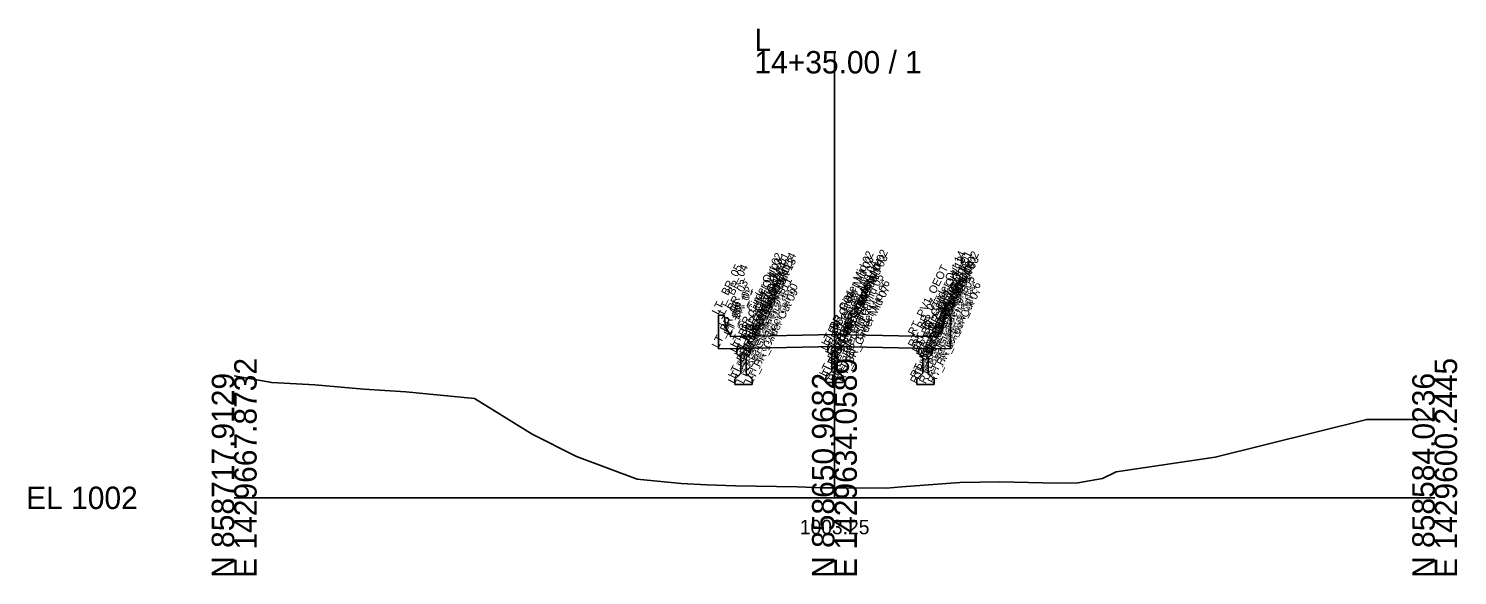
# Model space of a CAD drawing. Extents: x -26 to 2303, y -10 to 19558.
# Drawn here: x 1124.3 to 1302.8, y 16990.3 to 17058.6 of the extents above; entities that cross this region are included whole.
import ezdxf

# ---------------------------------------------------------------- set-up
doc = ezdxf.new("R2010")
doc.units = 0
for name, color, linetype in [('Default', 7, 'Continuous'), ('Exist Cross Section Cell', 7, 'Continuous'), ('Exist XS Center Line Elevation Label', 7, 'Continuous'), ('Exist XS Ground Line', 7, 'Continuous'), ('Prop CMT Concrete Structures', 7, 'Continuous'), ('Prop XS Dump Level', 7, 'Continuous')]:
    doc.layers.add(name, color=color, linetype=linetype)

msp = doc.modelspace()

# ---------------------------------------------------------------- linework, layer by layer
at = {"layer": 'Exist Cross Section Cell'}
for p, q in [((1225, 17000), (1225, 17055.83)), ((1150, 17000), (1225, 17000)), ((1225, 17000), (1300, 17000))]:
    msp.add_line(p, q, dxfattribs=at)
at = {"layer": 'Exist XS Ground Line'}
msp.add_lwpolyline([(1150, 17015.23), (1154.7, 17014.41), (1160.08, 17014.11), (1166.21, 17013.57), (1171.46, 17013.24), (1180.04, 17012.42), (1187.24, 17007.94), (1192.79, 17005.16), (1200.37, 17002.33), (1205.84, 17001.81), (1209.06, 17001.62), (1212.62, 17001.5), (1220.35, 17001.37), (1223.55, 17001.26), (1225, 17001.25), (1231.5, 17001.2), (1233.44, 17001.39), (1240.68, 17001.92), (1245.68, 17002.02), (1252.81, 17001.85), (1255.4, 17001.87), (1258.5, 17002.41), (1260.22, 17003.24), (1272.58, 17005.1), (1291.52, 17009.81), (1291.83, 17009.81), (1300, 17009.78)], dxfattribs=at)
at = {"layer": 'Prop CMT Concrete Structures'}
for points in [[(1225, 17020.4), (1215, 17020.2), (1212, 17020.14), (1211.99, 17020.39), (1211.41, 17021.22), (1211.24, 17022.81), (1210.5, 17022.81), (1210.5, 17018.61)], [(1225, 17020.4), (1235, 17020.2), (1238, 17020.14), (1238.01, 17020.39), (1238.59, 17021.22), (1238.76, 17022.81), (1239.5, 17022.81), (1239.5, 17018.61)], [(1225, 17018.9), (1225, 17020.4)], [(1225, 17018.9), (1225, 17020.4)], [(1210.5, 17018.61), (1215, 17018.7), (1225, 17018.9)], [(1214.46, 17018.69), (1213.62, 17018.67), (1212.79, 17018.66)], [(1212.79, 17018.66), (1212.79, 17018.01)], [(1212.79, 17018.01), (1213.29, 17017.51)], [(1213.96, 17017.51), (1214.46, 17018.01)], [(1214.46, 17018.01), (1214.46, 17018.69)], [(1225, 17018.9), (1224.17, 17018.88)], [(1224.17, 17018.88), (1224.17, 17018.23)], [(1224.17, 17018.23), (1224.67, 17017.73)], [(1224.67, 17017.73), (1224.67, 17015.82)], [(1225, 17014.4), (1225, 17018.9)], [(1225, 17018.9), (1225.83, 17018.88)], [(1225, 17014.4), (1225, 17018.9)], [(1239.5, 17018.61), (1235, 17018.7), (1225, 17018.9)], [(1225.83, 17018.23), (1225.33, 17017.73)], [(1225.33, 17017.73), (1225.33, 17015.82)], [(1225.83, 17018.88), (1225.83, 17018.23)], [(1235.54, 17018.69), (1236.38, 17018.67), (1237.21, 17018.66)], [(1235.54, 17018.01), (1235.54, 17018.69)], [(1236.04, 17017.51), (1235.54, 17018.01)], [(1237.21, 17018.01), (1236.71, 17017.51)], [(1237.21, 17018.66), (1237.21, 17018.01)], [(1213.29, 17017.51), (1213.29, 17015.59)], [(1213.96, 17015.59), (1213.96, 17017.51)], [(1236.04, 17015.59), (1236.04, 17017.51)], [(1236.71, 17017.51), (1236.71, 17015.59)], [(1213.29, 17015.59), (1212.54, 17014.84)], [(1212.54, 17014.84), (1212.54, 17014.17)], [(1212.54, 17014.17), (1213.62, 17014.17), (1214.71, 17014.17)], [(1214.71, 17014.84), (1213.96, 17015.59)], [(1214.71, 17014.17), (1214.71, 17014.84)], [(1224.67, 17015.82), (1223.92, 17015.07)], [(1223.92, 17015.07), (1223.92, 17014.4)], [(1223.92, 17014.4), (1225, 17014.4)], [(1226.08, 17014.4), (1225, 17014.4)], [(1225.33, 17015.82), (1226.08, 17015.07)], [(1226.08, 17015.07), (1226.08, 17014.4)], [(1235.29, 17014.84), (1236.04, 17015.59)], [(1235.29, 17014.17), (1235.29, 17014.84)], [(1237.46, 17014.17), (1236.38, 17014.17), (1235.29, 17014.17)], [(1236.71, 17015.59), (1237.46, 17014.84)], [(1237.46, 17014.84), (1237.46, 17014.17)]]:
    msp.add_lwpolyline(points, dxfattribs=at)

# ---------------------------------------------------------------- texts
at = {"layer": 'Default'}
msp.add_text('-', height=0.0001, dxfattribs=at).set_placement((1150, 17000))
at = {"layer": 'Exist Cross Section Cell'}
for s, p in [('L', (1215, 17055.83)), ('14+35.00 / 1', (1215, 17053.03)), ('EL 1002', (1124, 16998.6))]:
    msp.add_text(s, height=2.8, dxfattribs=at).set_placement(p)
for s, p in [('E 1429667.8732', (1152.8, 16990)), ('E 1429634.0589', (1227.8, 16990)), ('E 1429600.2445', (1302.8, 16990)), ('N 858717.9129', (1150, 16990)), ('N 858650.9682', (1225, 16990)), ('N 858584.0236', (1300, 16990))]:
    msp.add_text(s, height=2.8, rotation=90, dxfattribs=at).set_placement(p)
at = {"layer": 'Exist XS Center Line Elevation Label'}
msp.add_text('1003.25', height=1.8, dxfattribs=at).set_placement((1220.67, 16995.45))
at = {"layer": 'Prop XS Dump Level'}
for s, p in [('LT_BR_Girder Out 02', (1212.79, 17018.66)), ('LT_BR_Girder Out 01', (1213.62, 17018.67)), ('LT_BR_Girder Out 14', (1214.46, 17018.69)), ('LT_BR_Girder Mid 02', (1224.17, 17018.88)), ('RT_BR_Girder Mid 02', (1225.83, 17018.88)), ('RT_BR_Girder Mid 03', (1225.83, 17018.23)), ('RT_BR_Girder Out 14', (1235.54, 17018.69)), ('RT_BR_Girder Out 01', (1236.38, 17018.67)), ('RT_BR_Girder Out 02', (1237.21, 17018.66)), ('LT_ BR_05', (1210.5, 17022.81)), ('LT_ BR_04', (1211.24, 17022.81)), ('LT_BR_Girder Out 03', (1212.79, 17018.01)), ('LT_BR_Girder Out 04', (1213.29, 17017.51)), ('LT_BR_Girder Out 12', (1213.96, 17017.51)), ('LT_BR_Girder Out 13', (1214.46, 17018.01)), ('LT_PV1_OEOT', (1215, 17020.2)), ('LT_BR_Girder Mid 03', (1224.17, 17018.23)), ('LT_BR_Girder Mid 04', (1224.67, 17017.73)), ('RT_BR_Girder Mid 04', (1225.33, 17017.73)), ('RT_PV1_OEOT', (1235, 17020.2)), ('RT_BR_Girder Out 13', (1235.54, 17018.01)), ('RT_BR_Girder Out 12', (1236.04, 17017.51)), ('RT_BR_Girder Out 04', (1236.71, 17017.51)), ('RT_BR_Girder Out 03', (1237.21, 17018.01)), ('RT_ BR_04', (1238.76, 17022.81)), ('RT_ BR_05', (1239.5, 17022.81)), ('LT_BR_03', (1211.41, 17021.22)), ('LT_BR_Girder Out 06', (1212.54, 17014.84)), ('LT_BR_Girder Out 05', (1213.29, 17015.59)), ('LT_BR_Girder Out 11', (1213.96, 17015.59)), ('LT_BR_Girder Out 10', (1214.71, 17014.84)), ('LT_BR_Girder Mid 06', (1223.92, 17015.07)), ('LT_BR_Girder Mid 05', (1224.67, 17015.82)), ('RT_BR_Girder Mid 05', (1225.33, 17015.82)), ('RT_BR_Girder Mid 06', (1226.08, 17015.07)), ('RT_BR_Girder Out 10', (1235.29, 17014.84)), ('RT_BR_Girder Out 11', (1236.04, 17015.59)), ('RT_BR_Girder Out 05', (1236.71, 17015.59)), ('RT_BR_Girder Out 06', (1237.46, 17014.84)), ('RT_BR_03', (1238.59, 17021.22)), ('LT_BR_02', (1211.99, 17020.39)), ('LT_BR_01', (1212, 17020.14)), ('LT_BR_Girder Out 07', (1212.54, 17014.17)), ('LT_BR_Girder Out 08', (1213.62, 17014.17)), ('LT_BR_Girder Out 09', (1214.71, 17014.17)), ('LT_BR_Girder Mid 07', (1223.92, 17014.4)), ('PV1_PGL', (1225, 17020.4)), ('RT_BR_Girder Mid 07', (1226.08, 17014.4)), ('RT_BR_07', (1235, 17018.7)), ('RT_BR_Girder Out 09', (1235.29, 17014.17)), ('RT_BR_Girder Out 08', (1236.38, 17014.17)), ('RT_BR_Girder Out 07', (1237.46, 17014.17)), ('RT_BR_01', (1238, 17020.14)), ('RT_BR_02', (1238.01, 17020.39)), ('LT_BR_06', (1210.5, 17018.61)), ('LT_BR_07', (1215, 17018.7)), ('BR_Girder Mid 08', (1225, 17014.4)), ('BR_PGL', (1225, 17018.9)), ('RT_BR_06', (1239.5, 17018.61))]:
    msp.add_text(s, height=1, rotation=63.5833, dxfattribs=at).set_placement(p)

doc.saveas('drawing.dxf')
